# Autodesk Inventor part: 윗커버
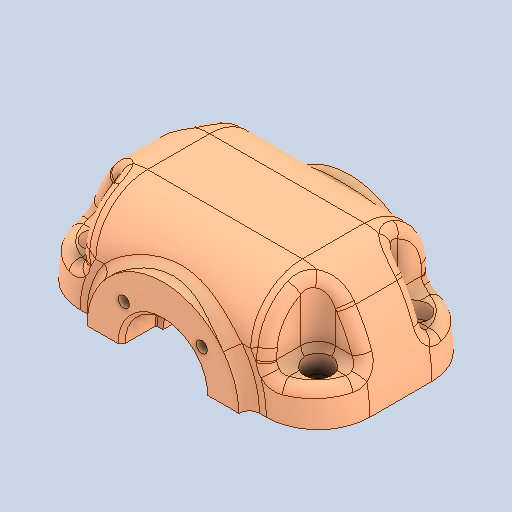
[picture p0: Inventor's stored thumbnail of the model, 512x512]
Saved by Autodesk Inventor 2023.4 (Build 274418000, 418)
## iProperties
Created: 2024-05
Part Number: 윗커버
Material: 알루미늄 6061
Document SubType Name: Modeling
Designer: edu-40
Density: 2.7 g/cm^3
Appearance: 기본값
Author: jhkim
Sending System: Autodesk Inventor 2025
Preprocessor: ST-DEVELOPER v20
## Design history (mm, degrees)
feature "솔리드1"
node "솔리드2"
